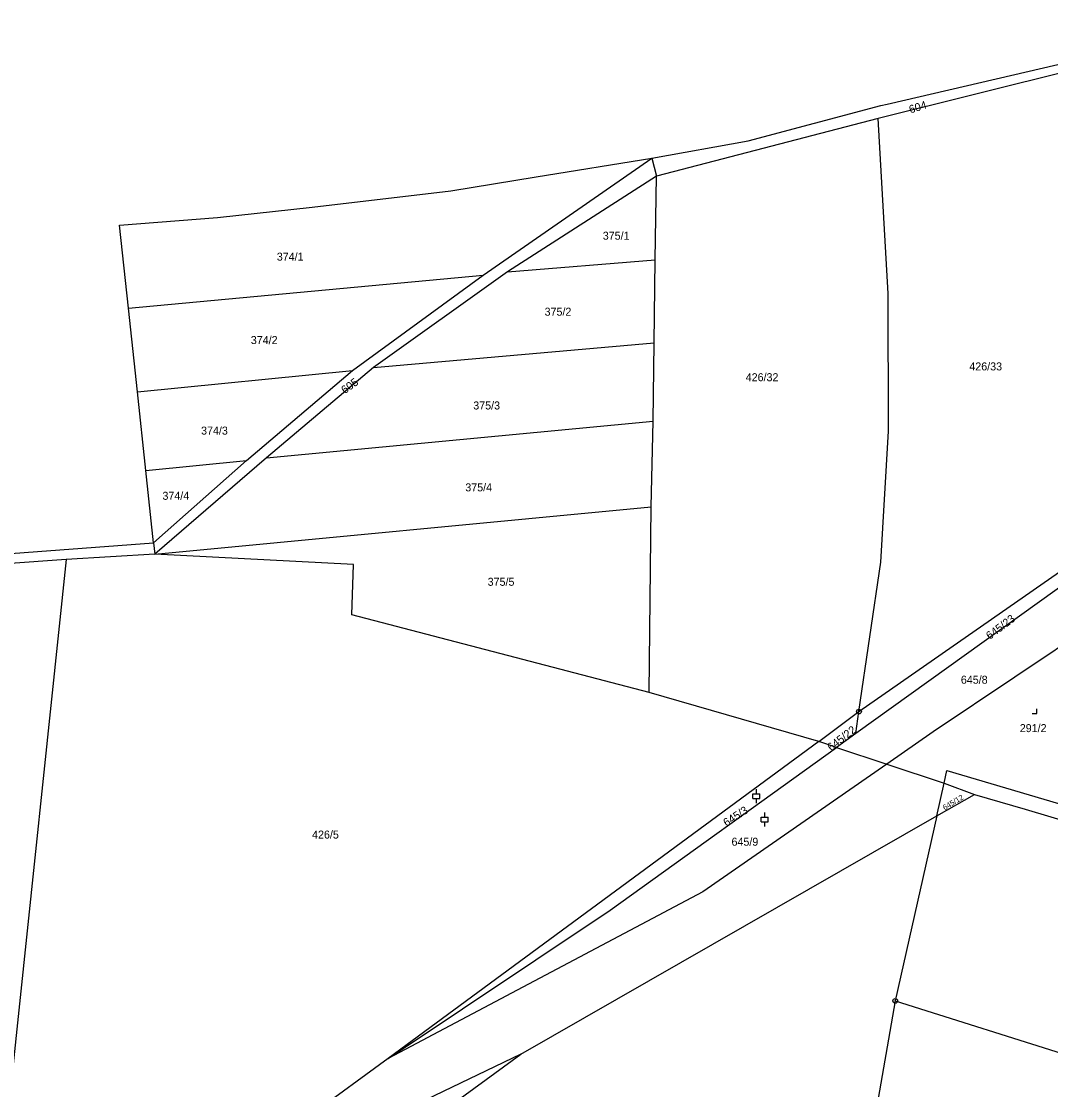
# Model space of a CAD drawing. Extents: x -758582 to -751794, y -998770 to -994350.
# Drawn here: x -756359.8 to -756141, y -994797.3 to -994570.3 of the extents above; entities that cross this region are included whole.
import ezdxf

# ---------------------------------------------------------------- set-up
doc = ezdxf.new("R2010")
doc.units = 0
for name, color, linetype in [('Hranice parcel', 7, 'Continuous'), ('Parcelní čísla', 7, 'Continuous'), ('Značky bodu BP', 7, 'Continuous'), ('Značky kultur', 7, 'Continuous')]:
    doc.layers.add(name, color=color, linetype=linetype)

msp = doc.modelspace()

# ---------------------------------------------------------------- linework, layer by layer
at = {"layer": 'Hranice parcel'}
for p, q in [((-756135.23, -994580.38), (-756177.65, -994590.94)), ((-756177.65, -994590.94), (-756224.81, -994603.15)), ((-756261.62, -994624.24), (-756225.75, -994599.36)), ((-756250.34, -994603.34), (-756225.75, -994599.36)), ((-756225.75, -994599.36), (-756224.81, -994603.15)), ((-756224.81, -994603.15), (-756256.43, -994623.49)), ((-756225.08, -994620.95), (-756224.81, -994603.15)), ((-756256.43, -994623.49), (-756225.08, -994620.95)), ((-756225.3, -994638.6), (-756225.08, -994620.95)), ((-756336.98, -994631.21), (-756261.62, -994624.24)), ((-756289.37, -994644.44), (-756261.62, -994624.24)), ((-756256.43, -994623.49), (-756284.92, -994643.85)), ((-756335.08, -994649.03), (-756336.98, -994631.21)), ((-756284.92, -994643.85), (-756225.3, -994638.6)), ((-756225.48, -994655.24), (-756225.3, -994638.6)), ((-756335.08, -994649.03), (-756289.37, -994644.44)), ((-756311.9, -994663.61), (-756289.37, -994644.44)), ((-756284.92, -994643.85), (-756307.69, -994663.02)), ((-756333.3, -994665.74), (-756335.08, -994649.03)), ((-756307.69, -994663.02), (-756225.48, -994655.24)), ((-756225.88, -994673.43), (-756225.48, -994655.24)), ((-756333.3, -994665.74), (-756311.9, -994663.61)), ((-756331.67, -994681.08), (-756311.9, -994663.61)), ((-756307.69, -994663.02), (-756331.36, -994683.49)), ((-756331.67, -994681.08), (-756333.3, -994665.74)), ((-756331.36, -994683.49), (-756225.88, -994673.43)), ((-756226.34, -994712.88), (-756225.88, -994673.43)), ((-756331.67, -994681.08), (-756331.36, -994683.49)), ((-756181.75, -994716.94), (-756131.3, -994681.73)), ((-756331.36, -994683.49), (-756350.2, -994684.66)), ((-756350.2, -994684.66), (-756361.78, -994794.51)), ((-756131.18, -994684.82), (-756182.4, -994721.61)), ((-756190.3, -994723.29), (-756226.34, -994712.88)), ((-756190.3, -994723.29), (-756181.75, -994716.94)), ((-756182.4, -994721.61), (-756181.75, -994716.94)), ((-756182.4, -994721.61), (-756186.55, -994724.59)), ((-756190.3, -994723.29), (-756281.77, -994790.62)), ((-756186.55, -994724.59), (-756190.3, -994723.29)), ((-756186.55, -994724.59), (-756175.85, -994728.13)), ((-756175.85, -994728.13), (-756163.68, -994732.16)), ((-756165.23, -994739.1), (-756163.68, -994732.16)), ((-756163.68, -994732.16), (-756157.18, -994734.57)), ((-756165.23, -994739.1), (-756157.18, -994734.57)), ((-756253.61, -994789.69), (-756165.23, -994739.1)), ((-756165.23, -994739.1), (-756174.03, -994778.41)), ((-756174.03, -994778.41), (-756182.33, -994825.28)), ((-756174.03, -994778.41), (-756101.26, -994801.32)), ((-756368.47, -994873.7), (-756253.61, -994789.69)), ((-756281.77, -994790.62), (-756367.18, -994852.8))]:
    msp.add_line(p, q, dxfattribs=at)
for points in [[(-756175.78, -994587.89), (-756139.51, -994579.42), (-756119.46, -994576.49), (-756083.96, -994570.29)], [(-756225.75, -994599.36), (-756205.29, -994595.69), (-756177.11, -994588.2), (-756175.78, -994587.89)], [(-756181.75, -994716.94), (-756177.11, -994685.16), (-756175.46, -994657.35), (-756175.56, -994628.13), (-756177.65, -994590.94)], [(-756336.98, -994631.21), (-756338.86, -994613.62), (-756318.09, -994611.98), (-756297.97, -994609.78), (-756268.46, -994606.27), (-756250.34, -994603.34)], [(-756547.9, -994684.31), (-756504.8, -994687.94), (-756444.14, -994688.97), (-756403.75, -994686.48), (-756331.67, -994681.08)], [(-756226.34, -994712.88), (-756289.51, -994696.4), (-756289.2, -994685.68), (-756331.36, -994683.49)], [(-756350.2, -994684.66), (-756403.54, -994688.45), (-756443.98, -994690.72), (-756502.87, -994690.02), (-756558.86, -994685.48)], [(-756131.26, -994698), (-756166.01, -994721.27), (-756175.85, -994728.13)], [(-756281.77, -994790.62), (-756234.66, -994759.15), (-756186.55, -994724.59)], [(-756175.85, -994728.13), (-756214.95, -994755.2), (-756281.77, -994790.62)], [(-756163.68, -994732.16), (-756163.07, -994729.45), (-756133.11, -994738.31)], [(-756157.18, -994734.57), (-756146.42, -994737.65), (-756089.29, -994754.74), (-756076.03, -994758.53)], [(-756253.61, -994789.69), (-756273.78, -994799.42), (-756368.18, -994869.46)]]:
    msp.add_lwpolyline(points, dxfattribs=at)
at = {"layer": 'Značky bodu BP'}
for centre, radius in [((-756181.75, -994716.94), 0.5), ((-756181.75, -994716.94), 0.0303), ((-756174.03, -994778.41), 0.5), ((-756174.03, -994778.41), 0.0303)]:
    msp.add_circle(centre, radius, dxfattribs=at)
at = {"layer": 'Značky kultur'}
for p, q in [((-756144.97, -994717.34), (-756143.97, -994717.34)), ((-756143.97, -994717.34), (-756143.97, -994716.34)), ((-756203.55, -994734.4), (-756203.55, -994733.4)), ((-756204.3, -994734.4), (-756202.8, -994734.4)), ((-756204.3, -994735.4), (-756204.3, -994734.4)), ((-756204.3, -994735.4), (-756202.8, -994735.4)), ((-756203.55, -994736.4), (-756203.55, -994735.4)), ((-756202.8, -994735.4), (-756202.8, -994734.4)), ((-756201.78, -994739.35), (-756201.78, -994738.35)), ((-756202.53, -994739.35), (-756201.03, -994739.35)), ((-756202.53, -994740.35), (-756202.53, -994739.35)), ((-756202.53, -994740.35), (-756201.03, -994740.35)), ((-756201.78, -994741.35), (-756201.78, -994740.35)), ((-756201.03, -994740.35), (-756201.03, -994739.35))]:
    msp.add_line(p, q, dxfattribs=at)

# ---------------------------------------------------------------- texts
at = {"layer": 'Parcelní čísla'}
for s, height, rotation, p in [('604', 1.7, 17, (-756170.82, -994589.87)), ('605', 1.7, 36, (-756291.02, -994649.52)), ('645/23', 1.7, 37, (-756153.97, -994701.73)), ('645/22', 1.7, 38, (-756187.66, -994725.42)), ('645/12', 1.14, 31, (-756163.53, -994737.95)), ('645/3', 1.7, 33, (-756209.92, -994741.43))]:
    msp.add_text(s, height=height, rotation=rotation, dxfattribs=at).set_placement(p)
for s, p in [('375/1', (-756236.2, -994616.68)), ('374/1', (-756305.47, -994621.13)), ('375/2', (-756248.56, -994632.83)), ('374/2', (-756310.99, -994638.85)), ('426/33', (-756158.3, -994644.45)), ('426/32', (-756205.82, -994646.75)), ('375/3', (-756263.72, -994652.75)), ('374/3', (-756321.56, -994658.09)), ('375/4', (-756265.41, -994670.15)), ('374/4', (-756329.77, -994671.94)), ('375/5', (-756260.66, -994690.21)), ('645/8', (-756160.1, -994711.02)), ('291/2', (-756147.58, -994721.3)), ('426/5', (-756297.97, -994743.92)), ('645/9', (-756208.84, -994745.44))]:
    msp.add_text(s, height=1.7, dxfattribs=at).set_placement(p)

doc.saveas('drawing.dxf')
